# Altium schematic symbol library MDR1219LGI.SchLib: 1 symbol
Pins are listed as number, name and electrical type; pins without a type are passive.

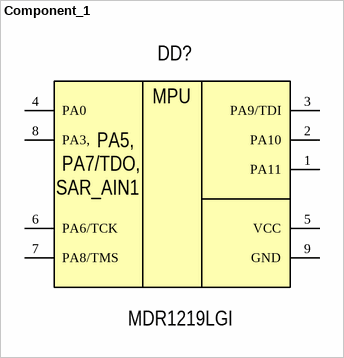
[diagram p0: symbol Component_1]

## Component_1
designator DD?, comment MDR1219LGI
pins: 1 PA11, 2 PA10, 3 PA9/TDI, 4 PA0, 5 VCC, 6 PA6/TCK, 7 PA8/TMS, 8 PA3,, 9 GND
